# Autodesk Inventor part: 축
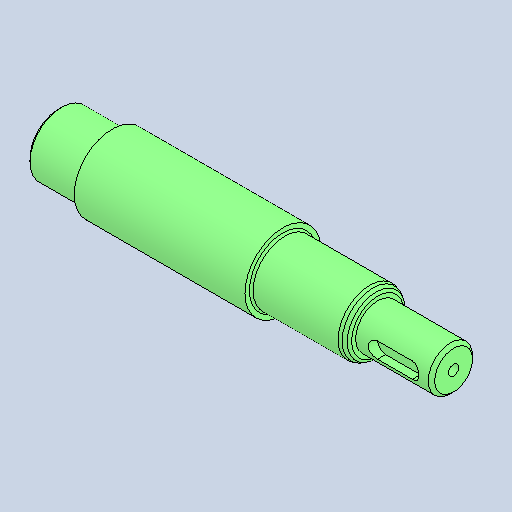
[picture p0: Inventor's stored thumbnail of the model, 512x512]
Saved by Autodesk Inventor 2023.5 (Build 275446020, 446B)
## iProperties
Created: 2026-07
Part Number: 축
Material: 강철, 탄소
Document SubType Name: Modeling
Designer: 1강의실14
Density: 7.85 g/cm^3
Appearance: 기본값
Author: jhkim
Sending System: Autodesk Inventor 2027
Preprocessor: ST-DEVELOPER v20.1
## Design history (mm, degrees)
node "축1"
node "솔리드2"
node "솔리드1"
